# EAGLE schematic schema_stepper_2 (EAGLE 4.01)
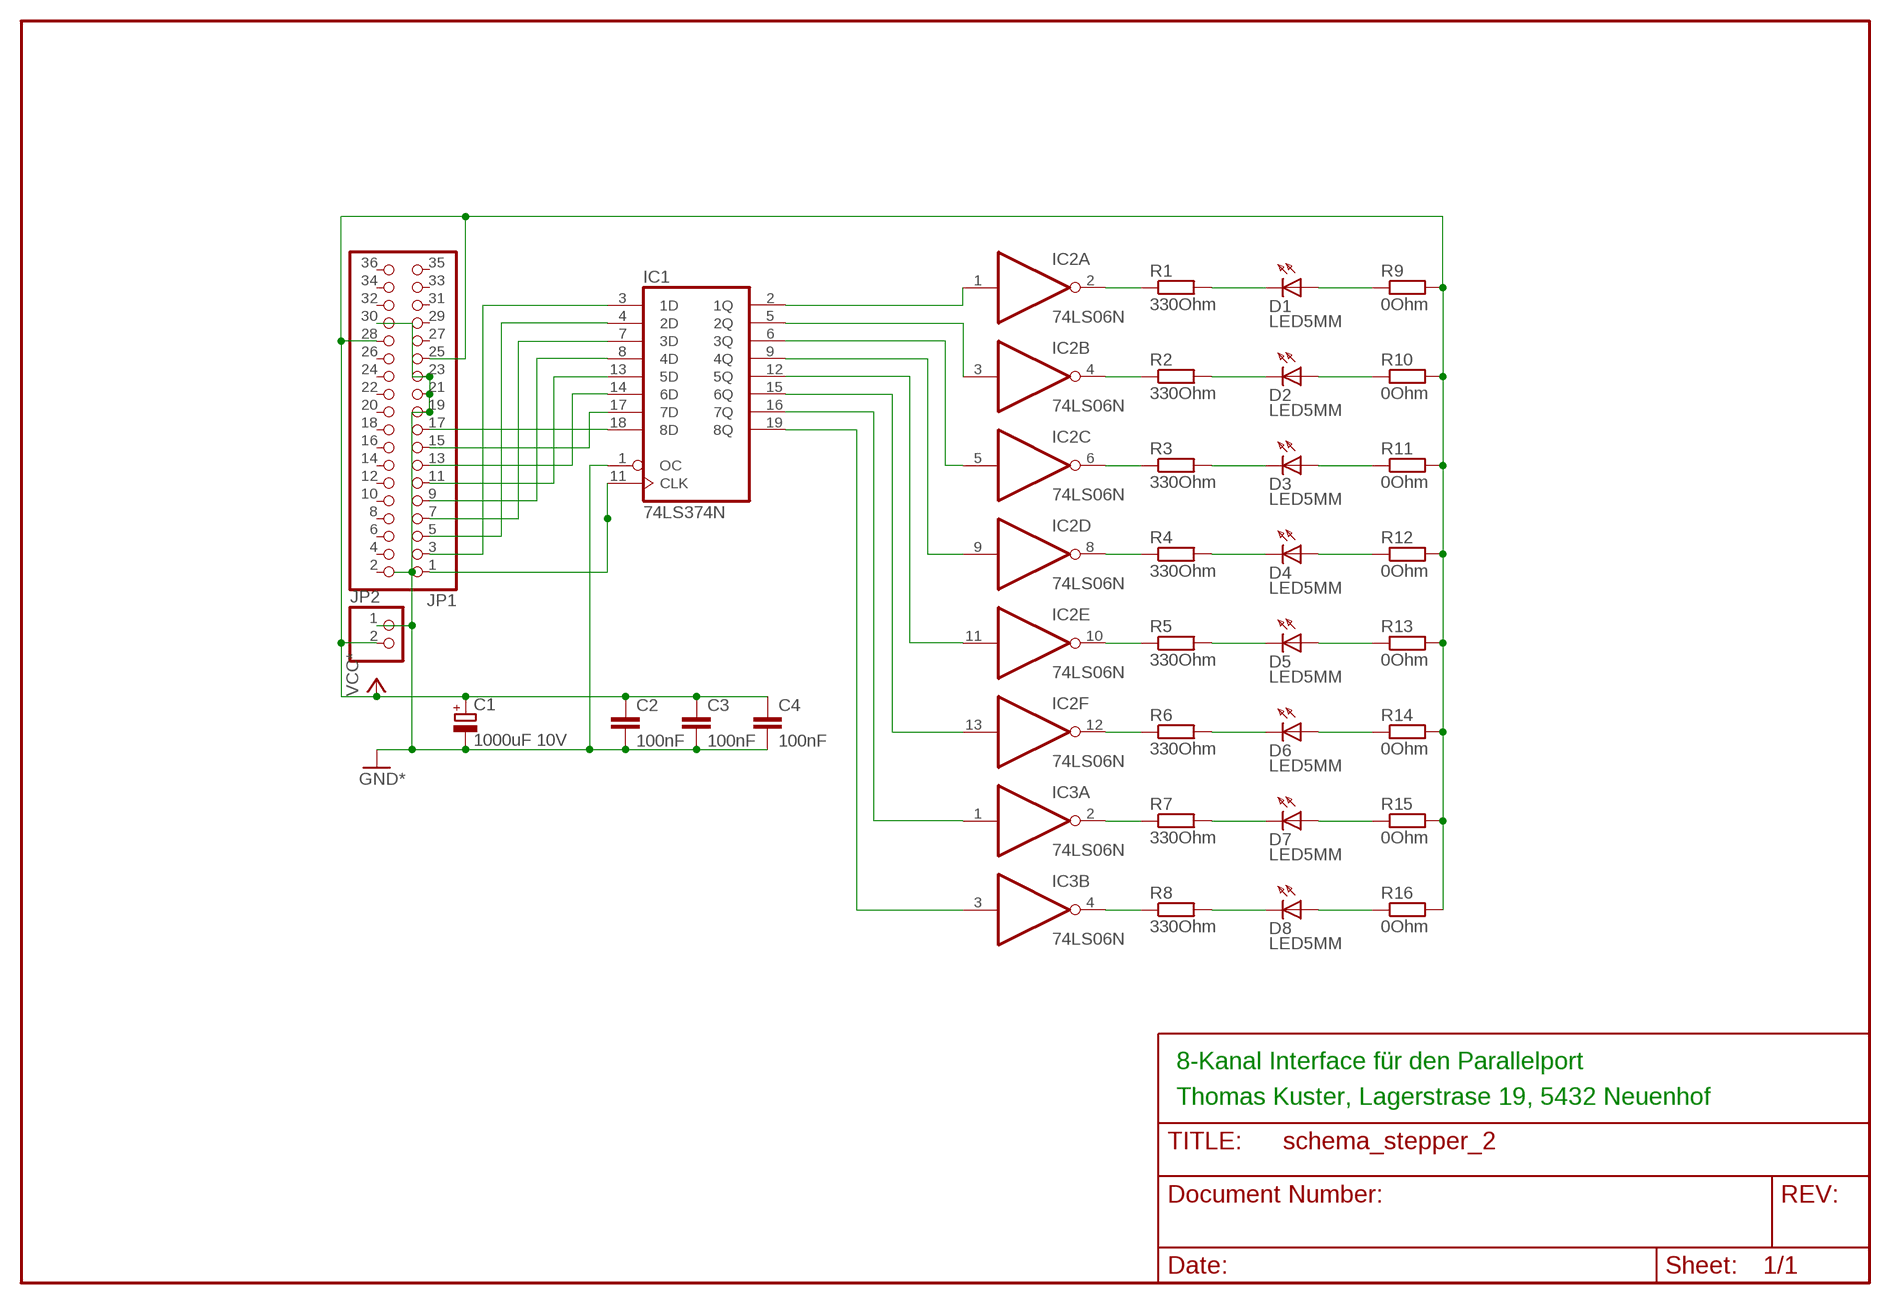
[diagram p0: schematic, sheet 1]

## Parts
C1  1000uF 10V  CPOL-EUE35-14AXIAL  [E35-14]
C2  100nF  C-EU025_050-035X075  [C025_050-035X075]
C3  100nF  C-EU025_050-035X075  [C025_050-035X075]
C4  100nF  C-EU025_050-035X075  [C025_050-035X075]
D1  LED5MM  [LED5MM]
D2  LED5MM  [LED5MM]
D3  LED5MM  [LED5MM]
D4  LED5MM  [LED5MM]
D5  LED5MM  [LED5MM]
D6  LED5MM  [LED5MM]
D7  LED5MM  [LED5MM]
D8  LED5MM  [LED5MM]
IC1  74LS374N  [DIL20]
IC2  74LS06N  [DIL14]
IC3  74LS06N  [DIL14]
JP1  PINHD-2X18  [2X18]
JP2  PINHD-1X2  [1X02]
R1  330Ohm  R-EU_0204/7  [0204/7]
R2  330Ohm  R-EU_0204/7  [0204/7]
R3  330Ohm  R-EU_0204/7  [0204/7]
R4  330Ohm  R-EU_0204/7  [0204/7]
R5  330Ohm  R-EU_0204/7  [0204/7]
R6  330Ohm  R-EU_0204/7  [0204/7]
R7  330Ohm  R-EU_0204/7  [0204/7]
R8  330Ohm  R-EU_0204/7  [0204/7]
R9  0Ohm  R-EU_0204/5  [0204/5]
R10  0Ohm  R-EU_0204/5  [0204/5]
R11  0Ohm  R-EU_0204/5  [0204/5]
R12  0Ohm  R-EU_0204/5  [0204/5]
R13  0Ohm  R-EU_0204/5  [0204/5]
R14  0Ohm  R-EU_0204/5  [0204/5]
R15  0Ohm  R-EU_0204/5  [0204/5]
R16  0Ohm  R-EU_0204/5  [0204/5]

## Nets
C3: C1.- C2.1 C3.1 C4.1 IC1.1(OC) JP1.19 JP1.21 JP1.23 JP1.30 JP2.1 ; supply symbol labelled GND*
N$1: IC1.2(1Q) IC2.1(A:I)
N$2: IC1.5(2Q) IC2.3(B:I)
N$3: IC1.6(3Q) IC2.5(C:I)
N$4: IC1.9(4Q) IC2.9(D:I)
N$5: IC1.12(5Q) IC2.11(E:I)
N$6: IC1.15(6Q) IC2.13(F:I)
N$7: IC1.16(7Q) IC3.1(A:I)
N$8: IC1.19(8Q) IC3.3(B:I)
N$9: IC3.4(B:O) R8.1
N$10: IC3.2(A:O) R7.1
N$11: IC2.12(F:O) R6.1
N$12: IC2.10(E:O) R5.1
N$13: IC2.8(D:O) R4.1
N$14: IC2.6(C:O) R3.1
N$15: IC2.4(B:O) R2.1
N$16: D2.K(C) R2.2
N$17: D3.K(C) R3.2
N$18: D4.K(C) R4.2
N$19: D5.K(C) R5.2
N$20: D6.K(C) R6.2
N$21: D7.K(C) R7.2
N$22: D8.K(C) R8.2
N$23: IC1.18(8D) JP1.17
N$24: IC1.17(7D) JP1.15
N$25: IC1.14(6D) JP1.13
N$26: IC1.13(5D) JP1.11
N$27: IC1.8(4D) JP1.9
N$28: IC1.7(3D) JP1.7
N$29: IC1.4(2D) JP1.5
N$30: IC1.3(1D) JP1.3
N$31: IC1.11(CLK) JP1.1
N$32: D1.A R9.1
N$33: D3.A R11.1
N$34: D4.A R12.1
N$35: D2.A R10.1
N$36: D1.K(C) R1.2
N$37: IC2.2(A:O) R1.1
N$39: D5.A R13.1
N$40: D6.A R14.1
N$41: D7.A R15.1
N$42: D8.A R16.1
VCC: C1.+ C2.2 C3.2 C4.2 JP1.25 JP1.28 JP2.2 R9.2 R10.2 R11.2 R12.2 R13.2 R14.2 R15.2 R16.2 ; supply symbol labelled VCC*
Unconnected: IC3.5(C:I) IC3.6(C:O) IC3.8(D:O) IC3.9(D:I) IC3.10(E:O) IC3.11(E:I) IC3.12(F:O) IC3.13(F:I) JP1.2 JP1.4 JP1.6 JP1.8 JP1.10 JP1.12 JP1.14 JP1.16 JP1.18 JP1.20 JP1.22 JP1.24 JP1.26 JP1.27 JP1.29 JP1.31 JP1.32 JP1.33 JP1.34 JP1.35 JP1.36

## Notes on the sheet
- 8-Kanal Interface für den Parallelport
- Thomas Kuster, Lagerstrase 19, 5432 Neuenhof

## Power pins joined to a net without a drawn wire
C3: IC1.10(GND) IC2.7(P:GND) IC3.7(P:GND)
VCC: IC1.20(VCC) IC2.14(P:VCC) IC3.14(P:VCC)

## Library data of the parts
C1 = rcl:CPOL-EU: POLARIZED CAPACITOR, European symbol
C2-C4 = rcl:C-EU: CAPACITOR, European symbol
D1-D8 = led:LED5MM: LED
IC1 = 74xx-eu:74*374: Octal D type transparent LATCH, edge triggered
IC2 IC3 = 74xx-eu:74*06: Hex INVERTER, open collector high-voltage output
JP1 = pinhead:PINHD-2X18: PIN HEADER
JP2 = pinhead:PINHD-1X2: PIN HEADER
R1-R16 = rcl:R-EU_: RESISTOR, European symbol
